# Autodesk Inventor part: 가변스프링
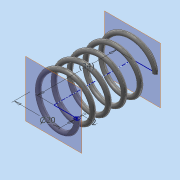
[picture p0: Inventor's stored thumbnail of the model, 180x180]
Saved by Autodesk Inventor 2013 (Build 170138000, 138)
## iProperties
Created: 2019-05
Part Number: 가변스프링
Material: 스테인리스강
Document SubType Name: Modeling
Designer: dgall
Density: 8.08 g/cm^3
Mass: 7.86239 g
Surface Area: 19.733 cm^2
Volume: 0.973069 cm^3
Author: dgall
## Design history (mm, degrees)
sketch "스케치1"
  geometry: L1 (10, 0)-(0, 0); L2 (0, 0)-(0, 34); L3 (0, 34)-(10, 34); C1 r 1 at (10, 0)
  constraints: 6 end point, 2 parallel, 1 centre point, 1 coincident, 1 horizontal, 1 perpendicular
  dimensions: "d0" = 34 distance of L1.end L2.end (derived); "d1" = 20 diameter of L1.start L2; "d2" = 2 diameter of C1
feature "코일1" sketch "스케치1" pitch "d3" = 10; turns "d5" = 5; dims "d4" = 34 (= d0), "d6" = 0, angle "d7" = 90 deg, angle "d8" = 90 deg, "d9" = 0, "d10" = 0
node "작업 평면2"
  node "작업 평면1"
feature "분할1"
feature "분할2"
node "솔리드1"
other parameters: "d11" = 0
